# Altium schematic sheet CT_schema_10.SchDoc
size 278 x 170 mm
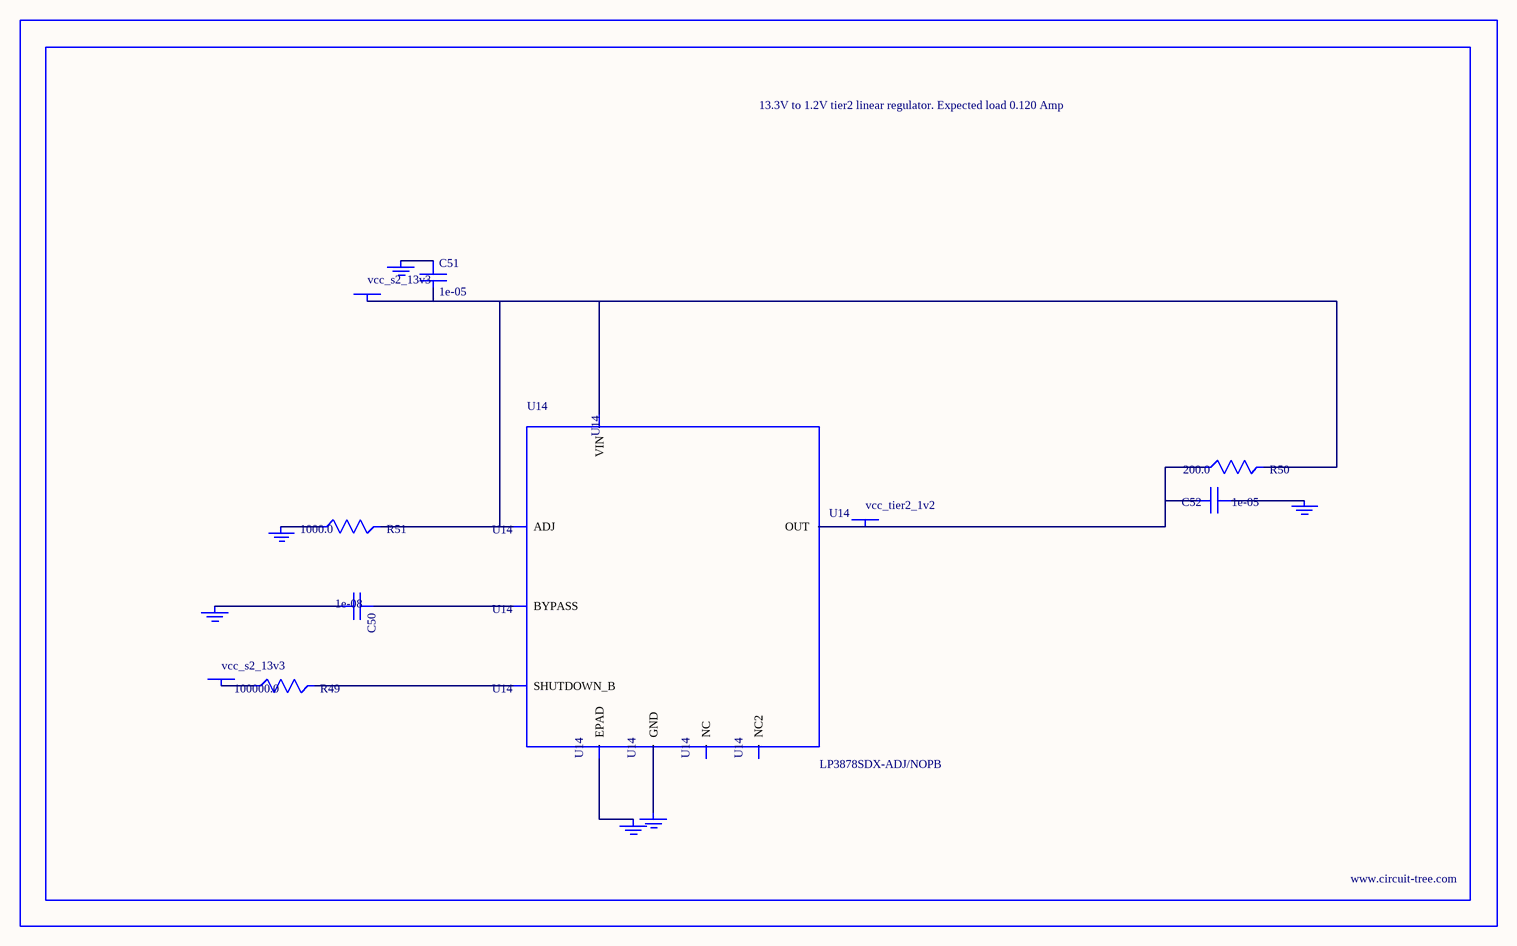
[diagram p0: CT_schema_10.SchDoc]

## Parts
BORDER9  (no value)
C50  1e-08  [C0402]
C51  1e-05  [C1210]
C52  1e-05  [C0805]
GND_INSTANCE_9_0  (no value)
GND_INSTANCE_9_1  (no value)
GND_INSTANCE_9_2  (no value)
GND_INSTANCE_9_3  (no value)
GND_INSTANCE_9_4  (no value)
GND_INSTANCE_9_5  (no value)
POWER_INSTANCE_9_0  vcc_s2_13v3
POWER_INSTANCE_9_1  vcc_s2_13v3
POWER_INSTANCE_9_2  vcc_tier2_1v2
R49  100000.0  [R0603]
R50  200.0  [R0603]
R51  1000.0  [R0603]
U14  LP3878SDX-ADJ/NOPB  [WSON-8]

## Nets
NetC50_1: C50.1 U14.1(BYPASS)
NetC50_2: C50.2 GND_INSTANCE_9_0.0(GND)
NetC51_1: C51.1 GND_INSTANCE_9_1.0(GND)
NetC51_2: C51.2 POWER_INSTANCE_9_0.0(PWR) R50.2 R51.2 U14.4(VIN) U14.6(ADJ)
NetC52_1: C52.1 GND_INSTANCE_9_2.0(GND)
NetC52_2: C52.2 POWER_INSTANCE_9_2.0(PWR) R50.1 U14.5(OUT)
NetGND_INSTANCE_9_3_0: GND_INSTANCE_9_3.0(GND) R51.1
NetGND_INSTANCE_9_4_0: GND_INSTANCE_9_4.0(GND) U14.PAD(EPAD)
NetGND_INSTANCE_9_5_0: GND_INSTANCE_9_5.0(GND) U14.3(GND)
NetPOWER_INSTANCE_9_1_0: POWER_INSTANCE_9_1.0(PWR) R49.1
NetR49_2: R49.2 U14.8(SHUTDOWN_B)

Not connected (* = marked no-connect by the designer): U14 2(NC) 7(NC2)

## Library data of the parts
BORDER9 = BORDER_PAGE9
C50 = C0402C103K3RAC
C51 = C1210C106K5PACTU
C52 = GRM219R60J106ME19D
GND_INSTANCE_9_0-GND_INSTANCE_9_5 = GND
POWER_INSTANCE_9_0-POWER_INSTANCE_9_2 = PWR
R49 = RC0603JR-07100KL
R50 = RC0603JR-07200RL
R51 = RC0603JR-071KL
